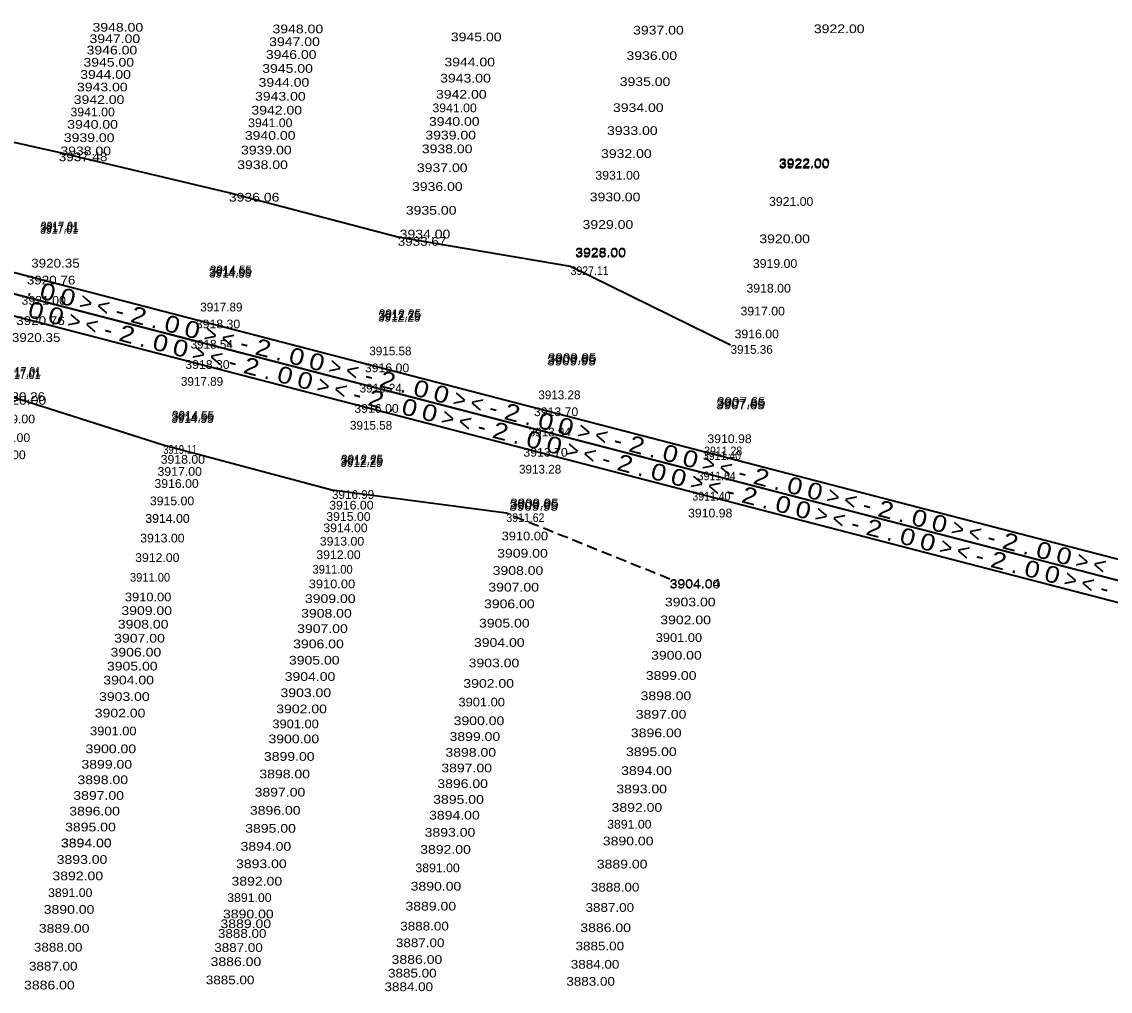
# Model space of a CAD drawing. Extents: x 49942 to 56479, y 47140 to 53283.
# Drawn here: x 55258 to 55882, y 49139 to 49694 of the extents above; entities that cross this region are included whole.
import ezdxf
from ezdxf.enums import TextEntityAlignment as Align

# ---------------------------------------------------------------- set-up
doc = ezdxf.new("R2010")
doc.units = 0
doc.header["$LTSCALE"] = 2
doc.linetypes.add('MEDIUM_DASHED', pattern=[4.5, 3, -1.5])
doc.layers.add('29', color=7, linetype='Continuous')
doc.layers.add('59', color=7, linetype='Continuous', lineweight=35)
doc.layers.add('63', color=7, linetype='Continuous', lineweight=35)

msp = doc.modelspace()

# ---------------------------------------------------------------- linework, layer by layer
at = {"layer": '59'}
for p, q in [((55279.721, 49619.507), (55182.067, 49641.315)), ((55377.029, 49596.37), (55279.721, 49619.507)), ((55473.776, 49571.071), (55377.029, 49596.37)), ((55572.734, 49554.284), (55473.776, 49571.071)), ((55664.335, 49509.17), (55572.734, 49554.284)), ((55339.507, 49451.903), (55244.044, 49482.144)), ((55436.114, 49426.064), (55339.507, 49451.903)), ((55535.99, 49412.815), (55436.114, 49426.064))]:
    msp.add_line(p, q, dxfattribs=at)
at = {"layer": '59', "linetype": 'MEDIUM_DASHED'}
msp.add_line((55629.517, 49375.117), (55535.99, 49412.815), dxfattribs=at)
at = {"layer": '63'}
for points in [[(54503.671, 49720.911), (56472.661, 49209.506), (56475.677, 49221.12), (54506.687, 49732.526)], [(54656.01, 49706.141), (56478.694, 49232.735), (56475.677, 49221.12), (54652.993, 49694.526)]]:
    msp.add_lwpolyline(points, close=True, dxfattribs=at)

# ---------------------------------------------------------------- texts
at = {"layer": '29'}
for s, width, p in [('3948.00', 1.2, (55298.991, 49688.699)), ('3948.00', 1.2, (55402.07, 49687.778)), ('3937.00', 1.2, (55608.52, 49687.066)), ('3922.00', 1.2, (55712.046, 49687.866)), ('3947.00', 1.2, (55297.296, 49682.173)), ('3947.00', 1.2, (55400.166, 49680.449)), ('3945.00', 1.2, (55504.196, 49683.192)), ('3946.00', 1.2, (55295.601, 49675.647)), ('3946.00', 1.2, (55398.263, 49673.121)), ('3945.00', 1.2, (55293.788, 49668.666)), ('3944.00', 1.2, (55500.465, 49668.827)), ('3936.00', 1.2, (55604.73, 49672.474)), ('3944.00', 1.2, (55291.974, 49661.685)), ('3945.00', 1.2, (55396.188, 49665.134)), ('3943.00', 1.2, (55290.107, 49654.494)), ('3944.00', 1.2, (55394.114, 49657.148)), ('3943.00', 1.2, (55498.063, 49659.577)), ('3935.00', 1.2, (55600.862, 49657.581)), ('3943.00', 1.2, (55392.046, 49649.188)), ('3942.00', 1.2, (55495.66, 49650.326)), ('3942.00', 1.2, (55288.239, 49647.303)), ('3941.00', 1.05, (55493.642, 49642.556)), ('3934.00', 1.2, (55596.994, 49642.688)), ('3941.00', 1.05, (55286.395, 49640.203)), ('3942.00', 1.2, (55389.979, 49641.227)), ('3940.00', 1.2, (55284.551, 49633.104)), ('3941.00', 1.05, (55388.105, 49634.015)), ('3940.00', 1.2, (55491.624, 49634.787)), ('3933.00', 1.2, (55593.576, 49629.528)), ('3939.00', 1.2, (55282.576, 49625.5)), ('3940.00', 1.2, (55386.225, 49626.773)), ('3939.00', 1.2, (55489.584, 49626.934)), ('3938.00', 1.2, (55280.601, 49617.896)), ('3939.00', 1.2, (55384.045, 49618.381)), ('3938.00', 1.2, (55487.545, 49619.081)), ('3937.48', 1.15, (55279.721, 49614.507)), ('3932.00', 1.2, (55590.158, 49616.367)), ('3922.00', 1.2, (55692.01, 49610.725)), ('3922.00', 1.2, (55692.117, 49611.134)), ('3938.00', 1.2, (55381.865, 49609.989)), ('3937.00', 1.2, (55484.74, 49608.283)), ('3922.00', 1.2, (55691.904, 49610.316)), ('3931.00', 1.05, (55586.933, 49603.95)), ('3936.00', 1.2, (55481.935, 49597.484)), ('3936.06', 1.2, (55377.029, 49591.37)), ('3930.00', 1.2, (55583.707, 49591.532)), ('3921.00', 1.05, (55686.351, 49588.935)), ('3935.00', 1.2, (55478.402, 49583.881)), ('3917.01', 0.9, (55269.177, 49573.911)), ('3917.01', 0.9, (55269.428, 49574.879)), ('3929.00', 1.2, (55579.61, 49575.755)), ('3917.01', 0.9, (55268.926, 49572.943)), ('3934.00', 1.2, (55474.869, 49570.278)), ('3920.00', 1.2, (55680.797, 49567.554)), ('3933.67', 1.15, (55473.776, 49566.071)), ('3928.00', 1.2, (55575.347, 49559.343)), ('3928.00', 1.2, (55575.429, 49559.66)), ('3928.00', 1.2, (55575.512, 49559.978)), ('3920.35', 1.15, (55263.898, 49553.585)), ('3927.11', 0.9, (55572.734, 49549.284)), ('3919.00', 1.05, (55677.121, 49553.399)), ('3920.76', 1.15, (55261.384, 49543.907)), ('3918.00', 1.05, (55673.445, 49539.244)), ('3921.00', 1.05, (55258.367, 49532.292)), ('3917.00', 1.05, (55670.044, 49526.153)), ('3920.76', 1.15, (55255.351, 49520.677)), ('3918.30', 1.05, (55358.172, 49518.768)), ('3920.35', 1.15, (55252.837, 49510.998)), ('3916.00', 1.05, (55666.645, 49513.063)), ('3909.95', 1.15, (55559.543, 49498.494)), ('3909.95', 1.15, (55559.794, 49499.462)), ('3918.30', 1.05, (55352.139, 49495.538)), ('3916.00', 1.05, (55454.961, 49493.629)), ('3909.95', 1.15, (55559.291, 49497.526)), ('3917.01', 0.9, (55247.306, 49489.705)), ('3917.01', 0.9, (55247.557, 49490.673)), ('3917.01', 0.9, (55247.809, 49491.641)), ('3920.00', 1.2, (55243.496, 49475.037)), ('3920.26', 1.15, (55244.044, 49477.144)), ('3907.65', 1.15, (55656.331, 49473.355)), ('3907.65', 1.15, (55656.583, 49474.323)), ('3916.00', 1.05, (55448.928, 49470.4)), ('3913.70', 1.05, (55551.75, 49468.49)), ('3907.65', 1.15, (55656.08, 49472.388)), ('3919.00', 1.05, (55240.717, 49464.335)), ('3918.00', 1.05, (55237.937, 49453.633)), ('3910.98', 1.05, (55651.052, 49453.03)), ('3917.00', 1.05, (55235.385, 49443.807)), ('3919.11', 0.8, (55339.507, 49446.903)), ('3913.70', 1.05, (55545.716, 49445.261)), ('3911.40', 0.9, (55648.538, 49443.351)), ('3911.28', 0.9, (55649.237, 49446.04)), ('3918.00', 1.05, (55338.024, 49441.192)), ('3917.00', 1.05, (55336.232, 49434.293)), ('3911.64', 0.9, (55645.522, 49431.736)), ('3916.00', 1.05, (55334.44, 49427.393)), ('3915.00', 1.05, (55331.848, 49417.416)), ('3911.40', 0.9, (55642.505, 49420.122)), ('3916.00', 1.05, (55434.53, 49414.966)), ('3909.95', 1.15, (55537.672, 49414.288)), ('3909.95', 1.15, (55537.923, 49415.256)), ('3909.95', 1.15, (55538.175, 49416.224)), ('3914.00', 1.05, (55329.225, 49407.314)), ('3914.00', 1.05, (55329.241, 49407.375)), ('3914.00', 1.05, (55329.256, 49407.436)), ('3915.00', 1.05, (55432.845, 49408.478)), ('3911.62', 0.9, (55535.991, 49407.815)), ('3910.98', 1.05, (55639.991, 49410.443)), ('3914.00', 1.05, (55431.16, 49401.991)), ('3913.00', 1.05, (55326.319, 49396.127)), ('3913.00', 1.05, (55429.158, 49394.283)), ('3910.00', 1.1, (55533.263, 49397.312)), ('3912.00', 1.05, (55427.156, 49386.577)), ('3909.00', 1.2, (55530.692, 49387.415)), ('3912.00', 1.05, (55323.413, 49384.94)), ('3911.00', 0.95, (55320.484, 49373.661)), ('3911.00', 0.95, (55424.985, 49378.217)), ('3908.00', 1.2, (55528.122, 49377.518)), ('3910.00', 1.1, (55422.814, 49369.857)), ('3907.00', 1.2, (55525.646, 49367.988)), ('3904.00', 1.2, (55629.417, 49369.732)), ('3904.04', 1.2, (55629.517, 49370.116)), ('3910.00', 1.1, (55317.555, 49362.382)), ('3909.00', 1.2, (55420.628, 49361.439)), ('3906.00', 1.2, (55523.171, 49358.458)), ('3903.00', 1.2, (55626.757, 49359.491)), ('3909.00', 1.2, (55315.527, 49354.577)), ('3908.00', 1.2, (55418.441, 49353.022)), ('3902.00', 1.2, (55624.097, 49349.249)), ('3908.00', 1.2, (55313.5, 49346.771)), ('3907.00', 1.2, (55416.167, 49344.265)), ('3905.00', 1.2, (55520.292, 49347.372)), ('3907.00', 1.2, (55311.418, 49338.758)), ('3904.00', 1.2, (55517.412, 49336.287)), ('3901.00', 1.1, (55621.465, 49339.116)), ('3906.00', 1.2, (55309.337, 49330.745)), ('3906.00', 1.2, (55413.892, 49335.509)), ('3905.00', 1.2, (55411.462, 49326.151)), ('3903.00', 1.2, (55514.371, 49324.578)), ('3900.00', 1.2, (55618.834, 49328.983)), ('3905.00', 1.2, (55307.264, 49322.761)), ('3904.00', 1.2, (55305.19, 49314.777)), ('3904.00', 1.2, (55409.032, 49316.793)), ('3902.00', 1.2, (55511.33, 49312.869)), ('3899.00', 1.2, (55615.822, 49317.39)), ('3903.00', 1.2, (55302.735, 49305.326)), ('3903.00', 1.2, (55406.624, 49307.524)), ('3898.00', 1.2, (55612.811, 49305.796)), ('3901.00', 1.1, (55508.554, 49302.181)), ('3902.00', 1.2, (55300.281, 49295.875)), ('3902.00', 1.2, (55404.217, 49298.255)), ('3897.00', 1.2, (55610.049, 49295.161)), ('3901.00', 1.1, (55401.986, 49289.667)), ('3900.00', 1.2, (55505.778, 49291.492)), ('3901.00', 1.1, (55297.62, 49285.63)), ('3900.00', 1.2, (55399.756, 49281.08)), ('3899.00', 1.2, (55503.424, 49282.43)), ('3896.00', 1.2, (55607.287, 49284.526)), ('3900.00', 1.2, (55294.959, 49275.385)), ('3899.00', 1.2, (55397.144, 49271.025)), ('3898.00', 1.2, (55501.07, 49273.365)), ('3895.00', 1.2, (55604.485, 49273.739)), ('3899.00', 1.2, (55292.657, 49266.524)), ('3897.00', 1.2, (55498.744, 49264.41)), ('3894.00', 1.2, (55601.683, 49262.952)), ('3898.00', 1.2, (55290.356, 49257.662)), ('3898.00', 1.2, (55394.533, 49260.97)), ('3896.00', 1.2, (55496.418, 49255.454)), ('3897.00', 1.2, (55391.828, 49250.558)), ('3893.00', 1.2, (55598.939, 49252.388)), ('3897.00', 1.2, (55288.022, 49248.68)), ('3895.00', 1.2, (55494.07, 49246.414)), ('3896.00', 1.2, (55285.689, 49239.696)), ('3896.00', 1.2, (55389.124, 49240.147)), ('3894.00', 1.2, (55491.722, 49237.374)), ('3892.00', 1.2, (55596.196, 49241.824)), ('3895.00', 1.2, (55283.327, 49230.601)), ('3891.00', 1.05, (55593.699, 49232.211)), ('3895.00', 1.2, (55386.445, 49229.833)), ('3893.00', 1.2, (55489.174, 49227.565)), ('3894.00', 1.2, (55280.934, 49221.39)), ('3894.00', 1.2, (55280.95, 49221.449)), ('3894.00', 1.2, (55280.965, 49221.506)), ('3894.00', 1.2, (55383.767, 49219.52)), ('3892.00', 1.2, (55486.626, 49217.755)), ('3890.00', 1.2, (55591.202, 49222.597)), ('3893.00', 1.2, (55278.496, 49212)), ('3893.00', 1.2, (55381.175, 49209.541)), ('3891.00', 1.05, (55483.889, 49207.217)), ('3889.00', 1.2, (55587.764, 49209.359)), ('3892.00', 1.2, (55276.057, 49202.611)), ('3892.00', 1.2, (55378.583, 49199.562)), ('3891.00', 1.05, (55273.561, 49193.001)), ('3890.00', 1.2, (55481.152, 49196.679)), ('3888.00', 1.15, (55584.325, 49196.121)), ('3891.00', 1.05, (55376.144, 49190.171)), ('3890.00', 1.2, (55271.065, 49183.391)), ('3890.00', 1.2, (55373.705, 49180.781)), ('3889.00', 1.2, (55478.186, 49185.259)), ('3887.00', 1.15, (55581.312, 49184.52)), ('3889.00', 1.2, (55372.256, 49175.202)), ('3889.00', 1.2, (55268.254, 49172.568)), ('3888.00', 1.15, (55370.807, 49169.624)), ('3888.00', 1.15, (55475.22, 49173.838)), ('3886.00', 1.2, (55578.299, 49172.919)), ('3888.00', 1.15, (55265.443, 49161.745)), ('3887.00', 1.15, (55472.736, 49164.275)), ('3885.00', 1.15, (55575.578, 49162.441)), ('3887.00', 1.15, (55368.712, 49161.556)), ('3887.00', 1.15, (55262.627, 49150.902)), ('3886.00', 1.2, (55366.616, 49153.489)), ('3886.00', 1.2, (55470.252, 49154.712)), ('3884.00', 1.15, (55572.856, 49151.964)), ('3885.00', 1.15, (55363.894, 49143.006)), ('3885.00', 1.15, (55468.226, 49146.909)), ('3886.00', 1.2, (55259.81, 49140.059)), ('3884.00', 1.15, (55466.199, 49139.107)), ('3883.00', 1.15, (55570.318, 49142.19))]:
    msp.add_text(s, height=5, dxfattribs=dict(at, width=width)).set_placement(p)
for s, p in [('3914.55', (55365.965, 49548.772)), ('3914.55', (55366.217, 49549.74)), ('3914.55', (55365.714, 49547.804)), ('3917.89', (55360.686, 49528.447)), ('3912.25', (55462.754, 49523.633)), ('3912.25', (55463.006, 49524.601)), ('3912.25', (55462.503, 49522.665)), ('3918.54', (55355.156, 49507.153)), ('3915.58', (55457.475, 49503.308)), ('3915.36', (55664.335, 49504.17)), ('3917.89', (55349.625, 49485.86)), ('3916.24', (55451.944, 49482.014)), ('3913.28', (55554.264, 49478.169)), ('3914.55', (55344.095, 49464.566)), ('3914.55', (55344.346, 49465.534)), ('3914.55', (55344.597, 49466.502)), ('3915.58', (55446.414, 49460.721)), ('3913.94', (55548.733, 49456.875)), ('3912.25', (55440.883, 49439.427)), ('3912.25', (55441.135, 49440.395)), ('3912.25', (55441.386, 49441.363)), ('3913.28', (55543.202, 49435.582)), ('3916.99', (55436.114, 49421.065))]:
    msp.add_text(s, height=5, dxfattribs=at).set_placement(p)
at = {"layer": '63'}
for s, width, p in [('0', 1.2, (55272.219, 49534.934)), ('0', 1.2, (55283.681, 49531.957)), ('>', 0.95, (55294.274, 49529.206)), ('0', 1.2, (55265.503, 49524.28)), ('0', 1.2, (55276.965, 49521.303)), ('<', 0.95, (55303.999, 49526.68)), ('-', 1.1, (55313.723, 49524.154)), ('2', 1.2, (55324.317, 49521.403)), ('>', 0.95, (55287.559, 49518.552)), ('<', 0.95, (55297.283, 49516.026)), ('0', 1.2, (55343.522, 49516.415)), ('0', 1.2, (55354.984, 49513.438)), ('-', 1.1, (55307.008, 49513.5)), ('2', 1.2, (55317.601, 49510.749)), ('>', 0.95, (55365.578, 49510.686)), ('0', 1.2, (55336.807, 49505.761)), ('0', 1.2, (55348.269, 49502.784)), ('<', 0.95, (55375.302, 49508.16)), ('-', 1.1, (55385.027, 49505.635)), ('2', 1.2, (55395.62, 49502.883)), ('>', 0.95, (55358.862, 49500.032)), ('<', 0.95, (55368.587, 49497.507)), ('0', 1.2, (55414.825, 49497.895)), ('0', 1.2, (55426.288, 49494.918)), ('-', 1.1, (55378.311, 49494.981)), ('2', 1.2, (55388.905, 49492.229)), ('0', 1.2, (55408.11, 49487.241)), ('>', 0.95, (55436.881, 49492.167)), ('0', 1.2, (55419.572, 49484.264)), ('<', 0.95, (55446.606, 49489.641)), ('-', 1.1, (55456.33, 49487.115)), ('2', 1.2, (55466.924, 49484.364)), ('>', 0.95, (55430.166, 49481.513)), ('<', 0.95, (55439.89, 49478.987)), ('0', 1.2, (55486.129, 49479.375)), ('0', 1.2, (55497.591, 49476.398)), ('-', 1.1, (55449.615, 49476.461)), ('2', 1.2, (55460.208, 49473.71)), ('0', 1.2, (55479.414, 49468.721)), ('>', 0.95, (55508.185, 49473.647)), ('0', 1.2, (55490.876, 49465.744)), ('<', 0.95, (55517.909, 49471.121)), ('-', 1.1, (55527.634, 49468.595)), ('2', 1.2, (55538.227, 49465.844)), ('>', 0.95, (55501.469, 49462.993)), ('<', 0.95, (55511.194, 49460.467)), ('0', 1.2, (55557.432, 49460.856)), ('0', 1.2, (55568.895, 49457.879)), ('-', 1.1, (55520.918, 49457.941)), ('2', 1.2, (55531.512, 49455.19)), ('0', 1.2, (55550.717, 49450.202)), ('>', 0.95, (55579.488, 49455.127)), ('<', 0.95, (55589.213, 49452.601)), ('0', 1.2, (55562.179, 49447.225)), ('-', 1.1, (55598.937, 49450.076)), ('2', 1.2, (55609.531, 49447.324)), ('>', 0.95, (55572.773, 49444.473)), ('<', 0.95, (55582.497, 49441.948)), ('0', 1.2, (55628.736, 49442.336)), ('0', 1.2, (55640.198, 49439.359)), ('-', 1.1, (55592.222, 49439.422)), ('2', 1.2, (55602.815, 49436.67)), ('0', 1.2, (55622.021, 49431.682)), ('>', 0.95, (55650.792, 49436.608)), ('<', 0.95, (55660.516, 49434.082)), ('0', 1.2, (55633.483, 49428.705)), ('-', 1.1, (55670.241, 49431.556)), ('2', 1.2, (55680.834, 49428.805)), ('>', 0.95, (55644.076, 49425.954)), ('<', 0.95, (55653.801, 49423.428)), ('0', 1.2, (55700.039, 49423.816)), ('0', 1.2, (55711.502, 49420.839)), ('-', 1.1, (55663.525, 49420.902)), ('2', 1.2, (55674.119, 49418.151)), ('0', 1.2, (55693.324, 49413.162)), ('>', 0.95, (55722.095, 49418.088)), ('<', 0.95, (55731.82, 49415.562)), ('0', 1.2, (55704.786, 49410.185)), ('>', 0.95, (55715.38, 49407.434)), ('-', 1.1, (55741.544, 49413.036)), ('2', 1.2, (55752.138, 49410.285)), ('<', 0.95, (55725.104, 49404.908)), ('0', 1.2, (55771.343, 49405.297)), ('0', 1.2, (55782.805, 49402.32)), ('-', 1.1, (55734.829, 49402.383)), ('2', 1.2, (55745.422, 49399.631)), ('0', 1.2, (55764.628, 49394.643)), ('>', 0.95, (55793.399, 49399.568)), ('<', 0.95, (55803.123, 49397.043)), ('0', 1.2, (55776.09, 49391.666)), ('>', 0.95, (55786.683, 49388.914)), ('-', 1.1, (55812.848, 49394.517)), ('2', 1.2, (55823.441, 49391.765)), ('<', 0.95, (55796.408, 49386.389)), ('0', 1.2, (55842.646, 49386.777)), ('0', 1.2, (55854.109, 49383.8)), ('-', 1.1, (55806.132, 49383.863)), ('2', 1.2, (55816.726, 49381.111)), ('0', 1.2, (55835.931, 49376.123)), ('>', 0.95, (55864.702, 49381.049)), ('<', 0.95, (55874.427, 49378.523)), ('0', 1.2, (55847.393, 49373.146)), ('>', 0.95, (55857.987, 49370.395)), ('<', 0.95, (55867.711, 49367.869)), ('-', 1.1, (55877.436, 49365.343))]:
    msp.add_text(s, height=9.6, rotation=345.44, dxfattribs=dict(at, width=width)).set_placement(p, align=Align.CENTER)
for p in [(55262.616, 49537.428), (55333.919, 49518.909), (55327.204, 49508.255), (55405.223, 49500.389), (55398.507, 49489.735), (55476.526, 49481.869), (55469.811, 49471.216), (55547.83, 49463.35), (55541.114, 49452.696), (55619.133, 49444.83), (55612.418, 49434.176), (55690.437, 49426.311), (55683.721, 49415.657), (55761.74, 49407.791), (55755.025, 49397.137), (55833.044, 49389.271), (55826.328, 49378.617)]:
    msp.add_text('.', height=9.6, rotation=345.44, dxfattribs=at).set_placement(p, align=Align.CENTER)

doc.saveas('drawing.dxf')
